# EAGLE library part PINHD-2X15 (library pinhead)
PIN HEADER
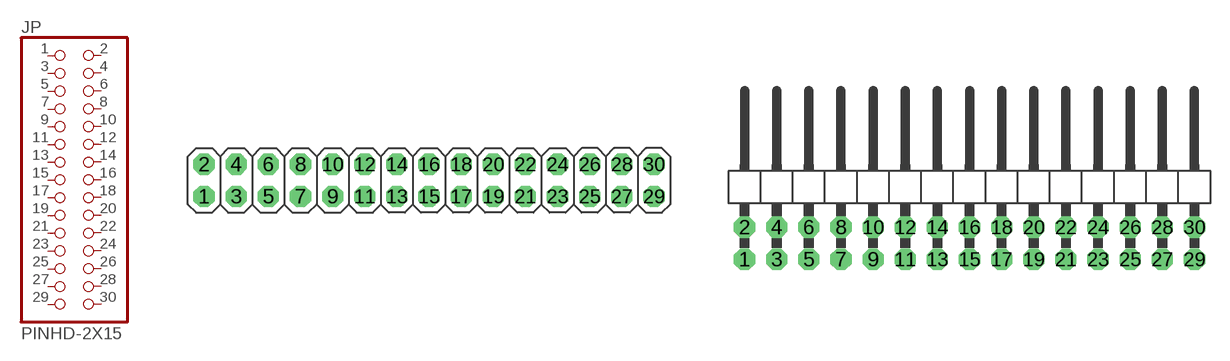
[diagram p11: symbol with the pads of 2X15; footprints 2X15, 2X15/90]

Designator prefix JP

## PINHD-2X15  [2X15]
1  1  pas
2  2  pas
3  3  pas
4  4  pas
5  5  pas
6  6  pas
7  7  pas
8  8  pas
9  9  pas
10  10  pas
11  11  pas
12  12  pas
13  13  pas
14  14  pas
15  15  pas
16  16  pas
17  17  pas
18  18  pas
19  19  pas
20  20  pas
21  21  pas
22  22  pas
23  23  pas
24  24  pas
25  25  pas
26  26  pas
27  27  pas
28  28  pas
29  29  pas
30  30  pas

## PINHD-2X15/90  [2X15/90]
Pads as for 2X15

## Footprint 2X15 (pad centres in mm)
PIN HEADER
drill 1.016 pad 1.67 octagon: 1 -17.78,-1.27; 2 -17.78,1.27; 3 -15.24,-1.27; 4 -15.24,1.27; 5 -12.7,-1.27; 6 -12.7,1.27; 7 -10.16,-1.27; 8 -10.16,1.27; 9 -7.62,-1.27; 10 -7.62,1.27; 11 -5.08,-1.27; 12 -5.08,1.27; 13 -2.54,-1.27; 14 -2.54,1.27; 15 0,-1.27; 16 0,1.27; 17 2.54,-1.27; 18 2.54,1.27; 19 5.08,-1.27; 20 5.08,1.27; 21 7.62,-1.27; 22 7.62,1.27; 23 10.16,-1.27; 24 10.16,1.27; 25 12.7,-1.27; 26 12.7,1.27; 27 15.24,-1.27; 28 15.24,1.27; 29 17.78,-1.27; 30 17.78,1.27

## Footprint 2X15/90 (pad centres in mm)
PIN HEADER
drill 1.016 pad 1.67 octagon: 1 -17.78,-6.35; 2 -17.78,-3.81; 3 -15.24,-6.35; 4 -15.24,-3.81; 5 -12.7,-6.35; 6 -12.7,-3.81; 7 -10.16,-6.35; 8 -10.16,-3.81; 9 -7.62,-6.35; 10 -7.62,-3.81; 11 -5.08,-6.35; 12 -5.08,-3.81; 13 -2.54,-6.35; 14 -2.54,-3.81; 15 0,-6.35; 16 0,-3.81; 17 2.54,-6.35; 18 2.54,-3.81; 19 5.08,-6.35; 20 5.08,-3.81; 21 7.62,-6.35; 22 7.62,-3.81; 23 10.16,-6.35; 24 10.16,-3.81; 25 12.7,-6.35; 26 12.7,-3.81; 27 15.24,-6.35; 28 15.24,-3.81; 29 17.78,-6.35; 30 17.78,-3.81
